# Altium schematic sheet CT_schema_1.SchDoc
size 544 x 491 mm
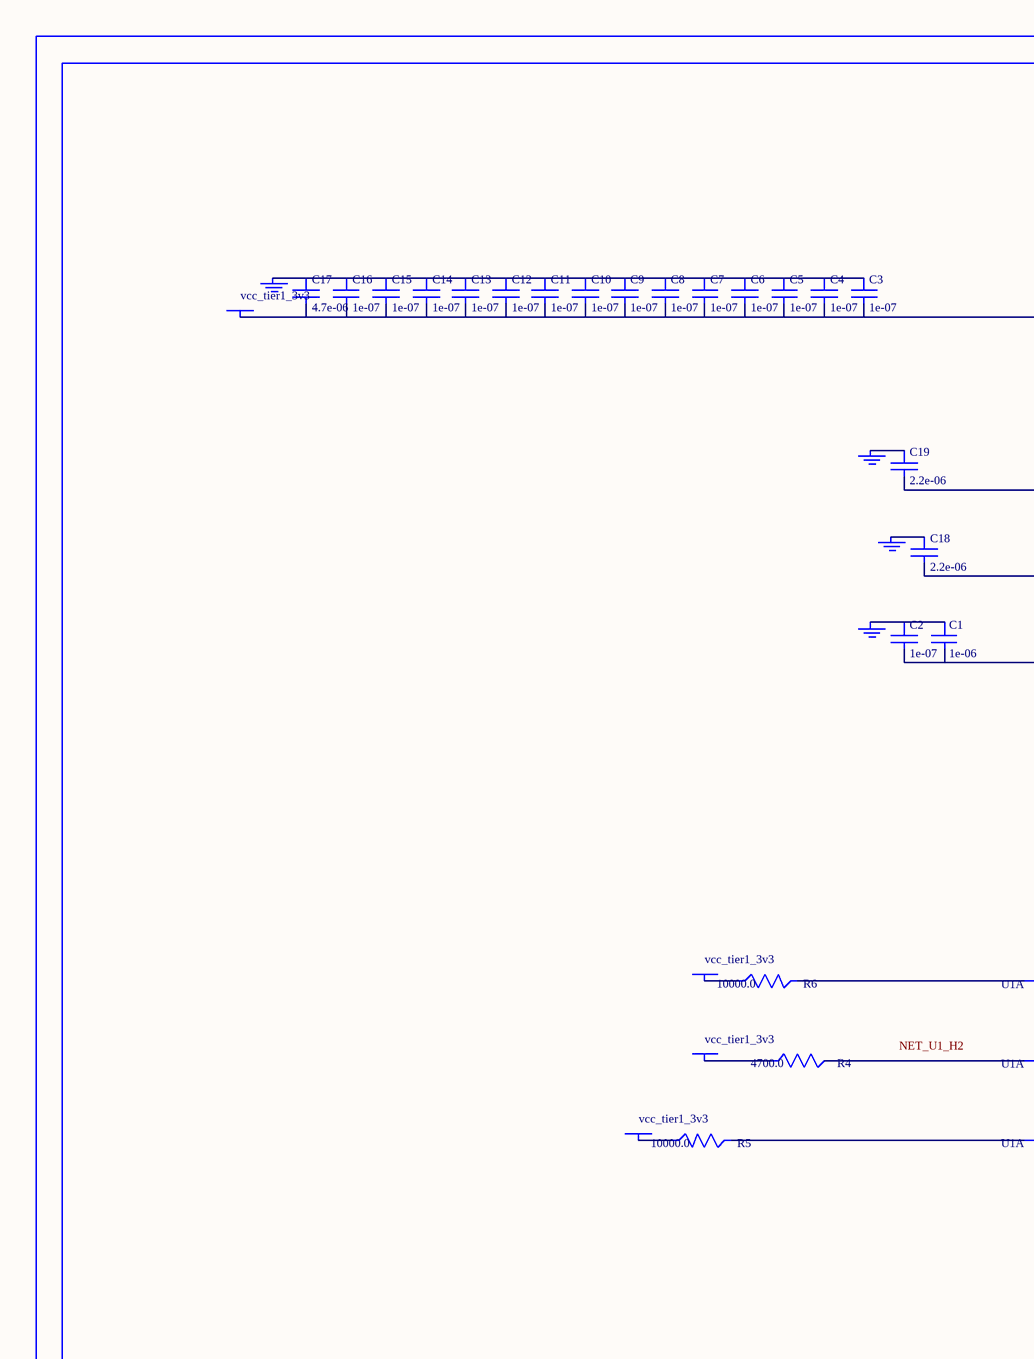
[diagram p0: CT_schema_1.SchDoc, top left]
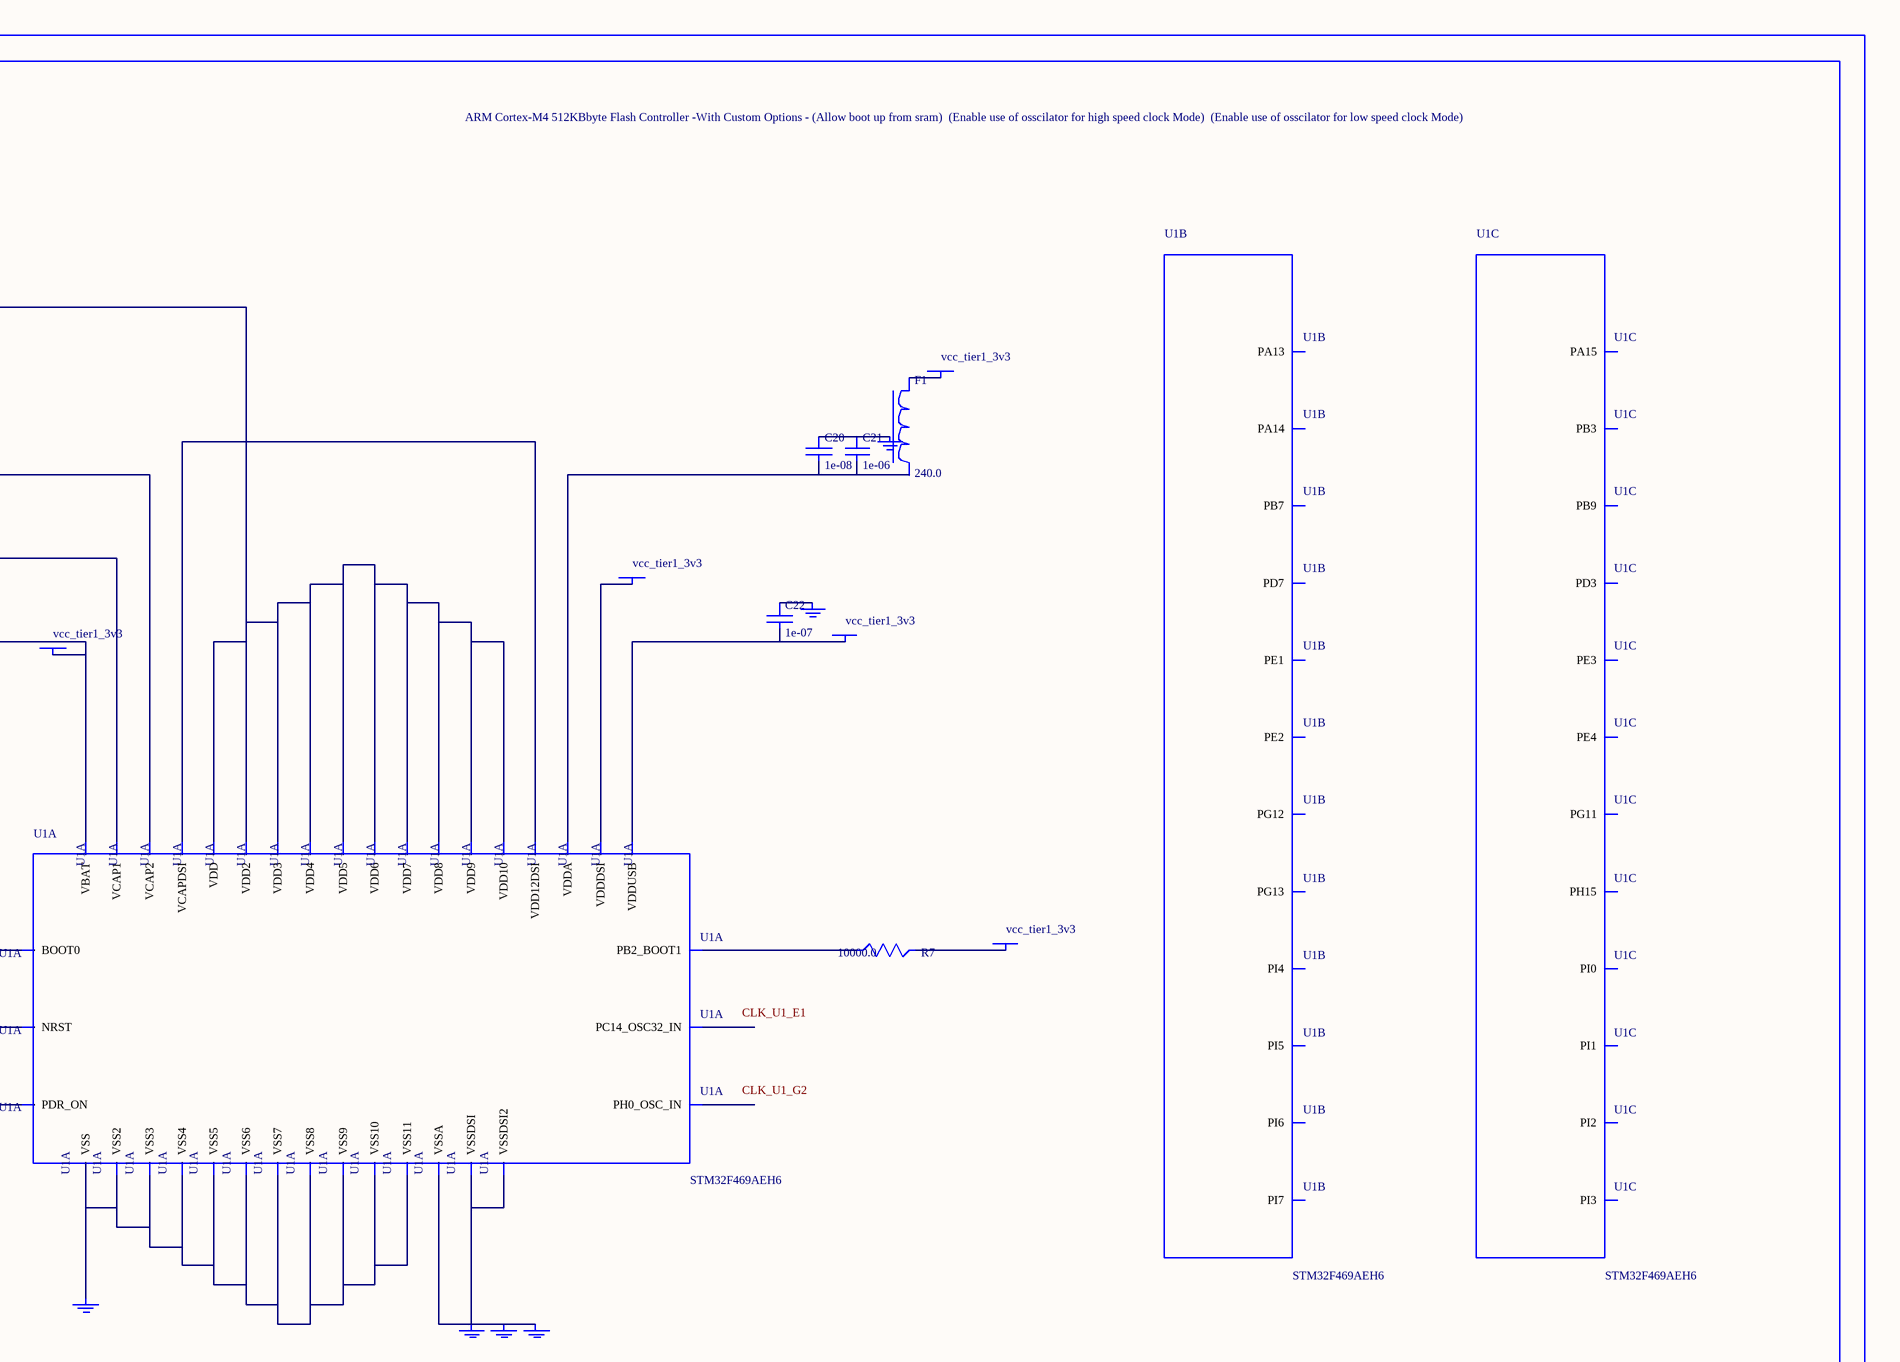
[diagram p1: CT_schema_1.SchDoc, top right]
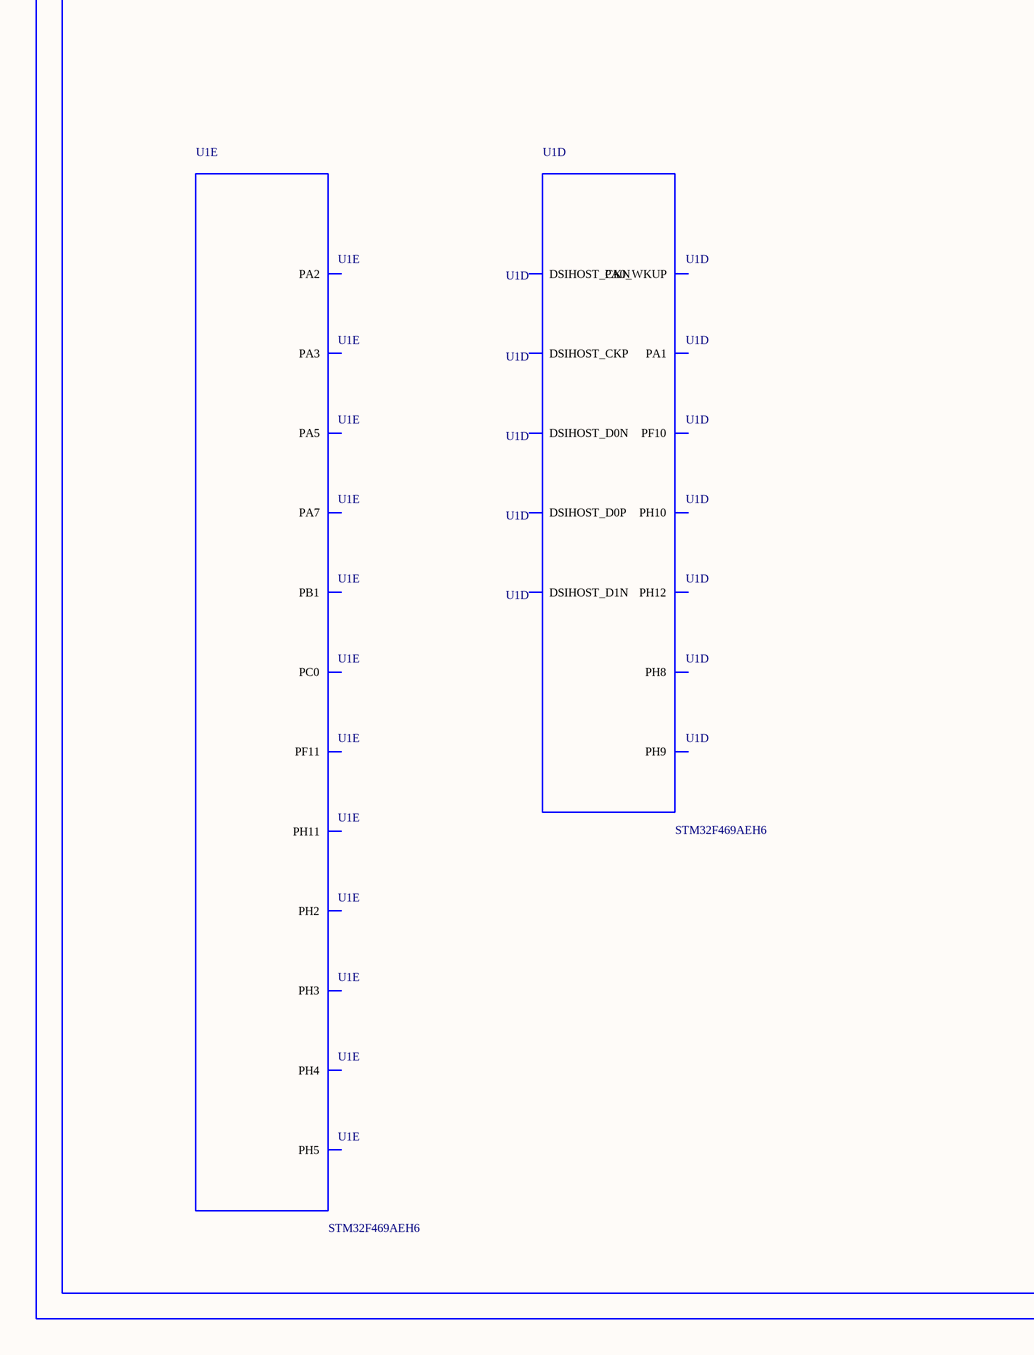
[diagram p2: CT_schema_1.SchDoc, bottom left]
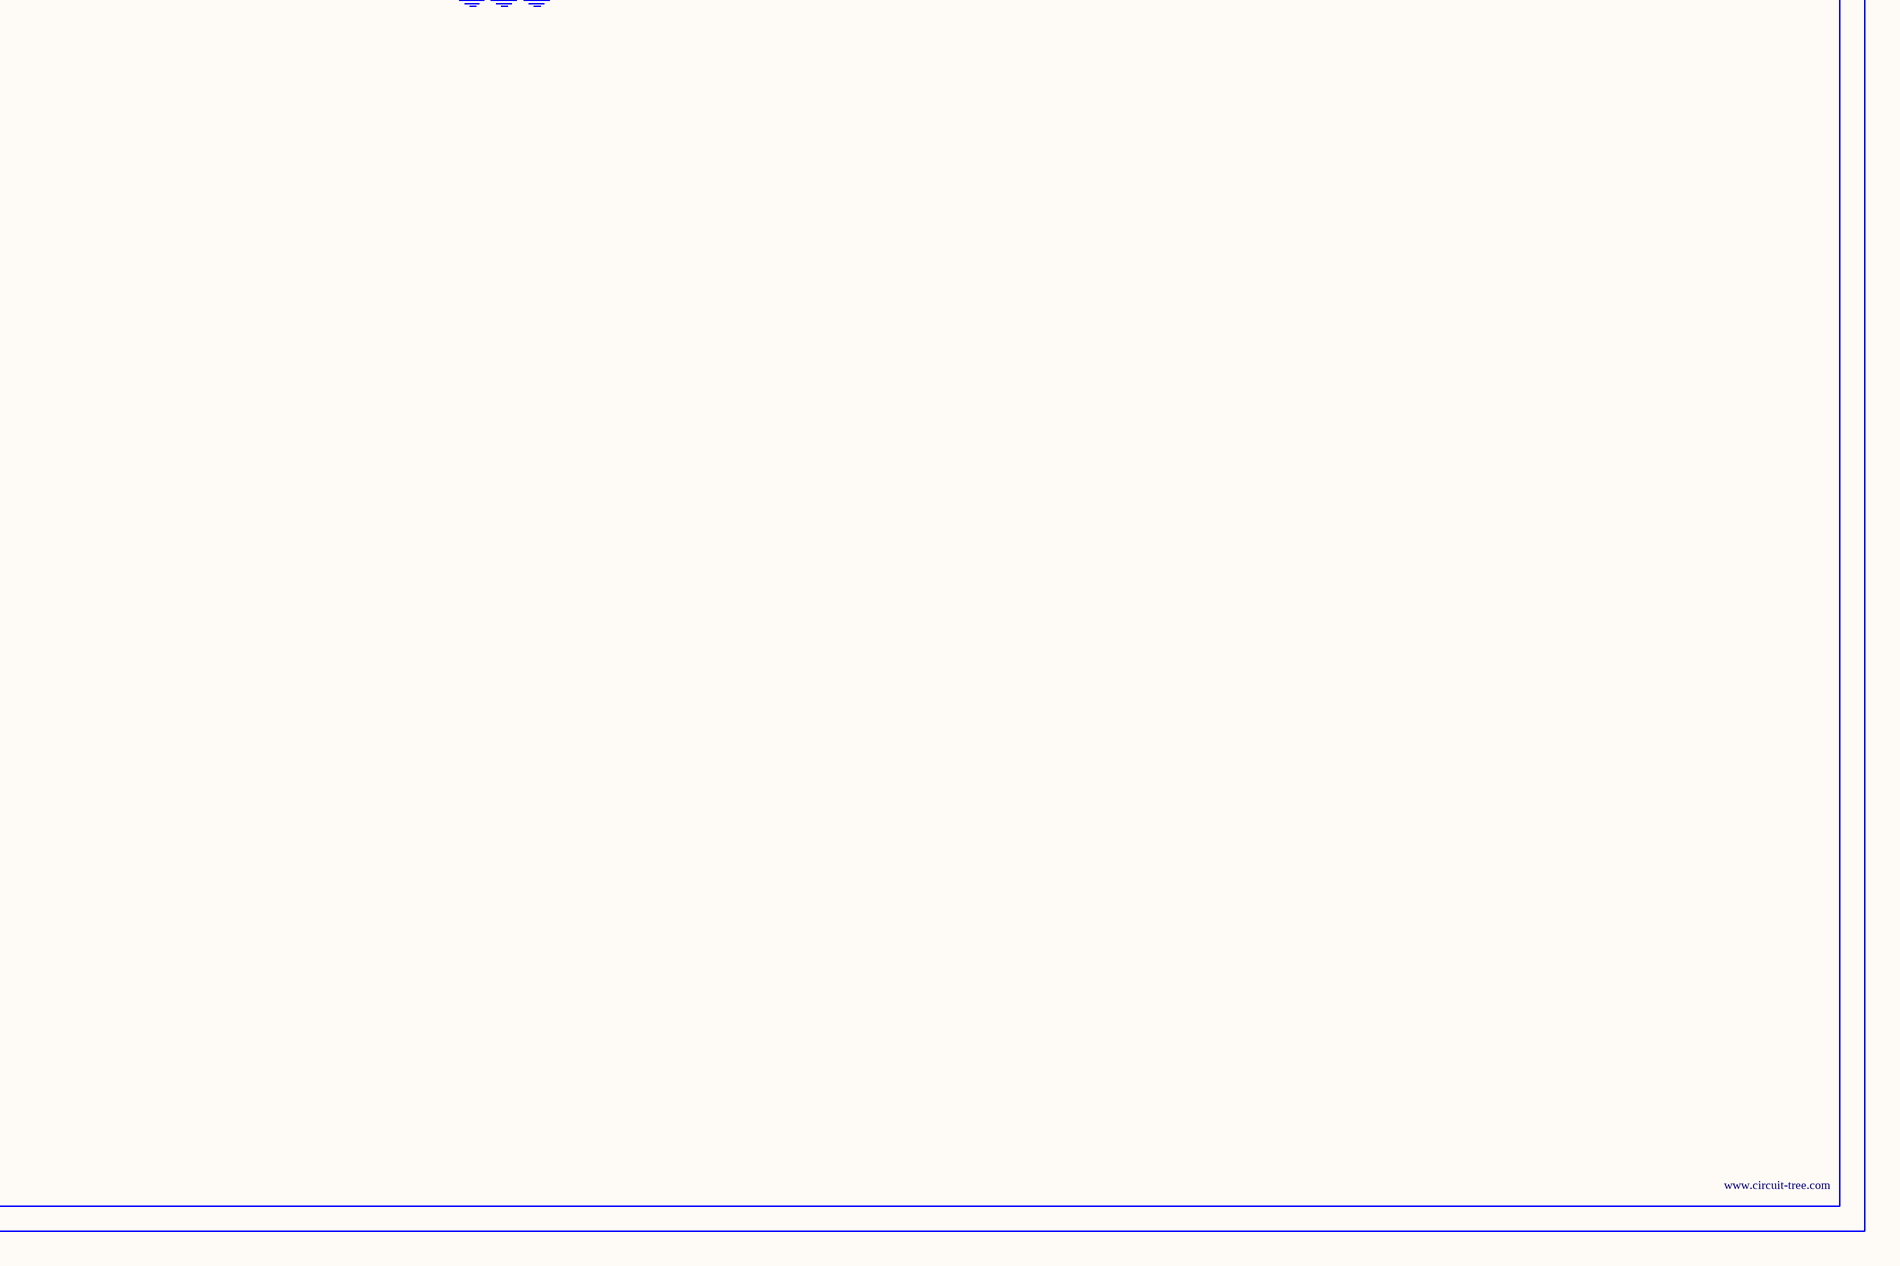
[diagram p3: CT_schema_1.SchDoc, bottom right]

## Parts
BORDER0  (no value)
C1  1e-06  [C0603]
C2  1e-07  [C0603]
C3  1e-07  [C0603]
C4  1e-07  [C0603]
C5  1e-07  [C0603]
C6  1e-07  [C0603]
C7  1e-07  [C0603]
C8  1e-07  [C0603]
C9  1e-07  [C0603]
C10  1e-07  [C0603]
C11  1e-07  [C0603]
C12  1e-07  [C0603]
C13  1e-07  [C0603]
C14  1e-07  [C0603]
C15  1e-07  [C0603]
C16  1e-07  [C0603]
C17  4.7e-06  [C0603]
C18  2.2e-06  [C0603]
C19  2.2e-06  [C0603]
C20  1e-08  [C0603]
C21  1e-06  [C0603]
C22  1e-07  [C0603]
F1  240.0  [L0603]
GND_INSTANCE_0_0  (no value)
GND_INSTANCE_0_1  (no value)
GND_INSTANCE_0_2  (no value)
GND_INSTANCE_0_3  (no value)
GND_INSTANCE_0_4  (no value)
GND_INSTANCE_0_5  (no value)
GND_INSTANCE_0_6  (no value)
GND_INSTANCE_0_7  (no value)
GND_INSTANCE_0_8  (no value)
GND_INSTANCE_0_9  (no value)
POWER_INSTANCE_0_0  vcc_tier1_3v3
POWER_INSTANCE_0_1  vcc_tier1_3v3
POWER_INSTANCE_0_2  vcc_tier1_3v3
POWER_INSTANCE_0_3  vcc_tier1_3v3
POWER_INSTANCE_0_4  vcc_tier1_3v3
POWER_INSTANCE_0_5  vcc_tier1_3v3
POWER_INSTANCE_0_6  vcc_tier1_3v3
POWER_INSTANCE_0_7  vcc_tier1_3v3
POWER_INSTANCE_0_8  vcc_tier1_3v3
R4  4700.0  [R0603]
R5  10000.0  [R0603]
R6  10000.0  [R0603]
R7  10000.0  [R0603]
U1  STM32F469AEH6  [UFBGA169]  (parts A,B,C,D,E of 14)

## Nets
NetC1_1: C1.1 C2.1 GND_INSTANCE_0_0.0(GND)
NetC1_2: C1.2 C2.2 POWER_INSTANCE_0_0.0(PWR) U1.E5(VBAT)
NetC3_1: C3.1 C4.1 C5.1 C6.1 C7.1 C8.1 C9.1 C10.1 C11.1 C12.1 C13.1 C14.1 C15.1 C16.1 C17.1 GND_INSTANCE_0_2.0(GND)
NetC3_2: C3.2 C4.2 C5.2 C6.2 C7.2 C8.2 C9.2 C10.2 C11.2 C12.2 C13.2 C14.2 C15.2 C16.2 C17.2 POWER_INSTANCE_0_2.0(PWR) U1.D3(VDD2) U1.D10(VDD) U1.F4(VDD3) U1.F7(VDD4) U1.G8(VDD5) U1.J4(VDD6) U1.K6(VDD8) U1.K10(VDD7) U1.L6(VDD9) U1.L9(VDD10)
NetC18_1: C18.1 GND_INSTANCE_0_3.0(GND)
NetC18_2: C18.2 U1.N9(VCAP1)
NetC19_1: C19.1 GND_INSTANCE_0_4.0(GND)
NetC19_2: C19.2 U1.D12(VCAP2)
NetC20_1: C20.1 C21.1 GND_INSTANCE_0_1.0(GND)
NetC20_2: C20.2 C21.2 U1.J3(VDDA)
NetC22_1: C22.1 GND_INSTANCE_0_5.0(GND)
NetC22_2: C22.2 POWER_INSTANCE_0_4.0(PWR) U1.G11(VDDUSB)
NetF1_1: F1.1 POWER_INSTANCE_0_1.0(PWR)
NetGND_INSTANCE_0_6_0: GND_INSTANCE_0_6.0(GND) GND_INSTANCE_0_7.0(GND) GND_INSTANCE_0_8.0(GND) U1.H11(VSSDSI) U1.J2(VSSA) U1.K11(VSSDSI2)
NetGND_INSTANCE_0_9_0: GND_INSTANCE_0_9.0(GND) U1.D11(VSS) U1.E3(VSS2) U1.F5(VSS3) U1.F8(VSS4) U1.G7(VSS5) U1.G9(VSS6) U1.J1(VSS7) U1.J6(VSS9) U1.J7(VSS10) U1.J10(VSS8) U1.M9(VSS11)
NetPOWER_INSTANCE_0_3_0: POWER_INSTANCE_0_3.0(PWR) R5.1
NetPOWER_INSTANCE_0_5_0: POWER_INSTANCE_0_5.0(PWR) R6.1
NetPOWER_INSTANCE_0_6_0: POWER_INSTANCE_0_6.0(PWR) R7.2
NetPOWER_INSTANCE_0_7_0: POWER_INSTANCE_0_7.0(PWR) U1.K13(VDDDSI)
NetPOWER_INSTANCE_0_8_0: POWER_INSTANCE_0_8.0(PWR) R4.1
NetR4_2: R4.2 U1.H2(NRST)
NetR5_2: R5.2 U1.C3(PDR_ON)
NetR6_2: R6.2 U1.A5(BOOT0)
NetR7_1: R7.1 U1.L5(PB2_BOOT1)
NetU1_J11: U1.J11(VDD12DSI) U1.K12(VCAPDSI)

Not connected (* = marked no-connect by the designer): F1 2; U1 A1(PI6) A2(PI5) A3(PE1) A6(PG13) A7(PG12) A8(PD7) A10(PA14) A11(PA13) B1(PI7) B2(PE2) B3(PI4) B4(PB7) B5(PB3) B6(PG11) B10(PI3) B11(PA15) B12(PI2) B13(PI0) C1(PE3) C2(PE4) C4(PB9) C8(PD3) C11(PI1) C12(PH15) E1(PC14_OSC32_IN) G2(PH0_OSC_IN) G13(DSIHOST_D1N) H1(PF10) H8(PH8) H9(PH9) H10(PH12) H12(DSIHOST_CKP) H13(DSIHOST_CKN) J5(PA0_WKUP) J9(PH10) J12(DSIHOST_D0P) J13(DSIHOST_D0N) K1(PA1) K2(PA2) K3(PA3) K4(PA7) K5(PB1) K9(PH11) L1(PH3) L2(PH2) L3(PH5) M1(PC0) M2(PH4) M3(PA5) M5(PF11)

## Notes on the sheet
- Labels drawn without touching a wire or pin: CLK_U1_E1, CLK_U1_G2, NET_U1_H2

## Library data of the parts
BORDER0 = BORDER_PAGE0
C1 C21 = C0603C105K3RACTU
C2-C16 C22 = 06035C104K4Z2A
C17 = GRM188R6YA475KE15D
C18 C19 = C0603C225K8RACTU
C20 = 06035C103K4Z2A
F1 = Z0603C241ASMST
GND_INSTANCE_0_0-GND_INSTANCE_0_9 = GND
POWER_INSTANCE_0_0-POWER_INSTANCE_0_8 = PWR
R4 = RC0603JR-074K7L
R5-R7 = RC0603JR-0710KL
